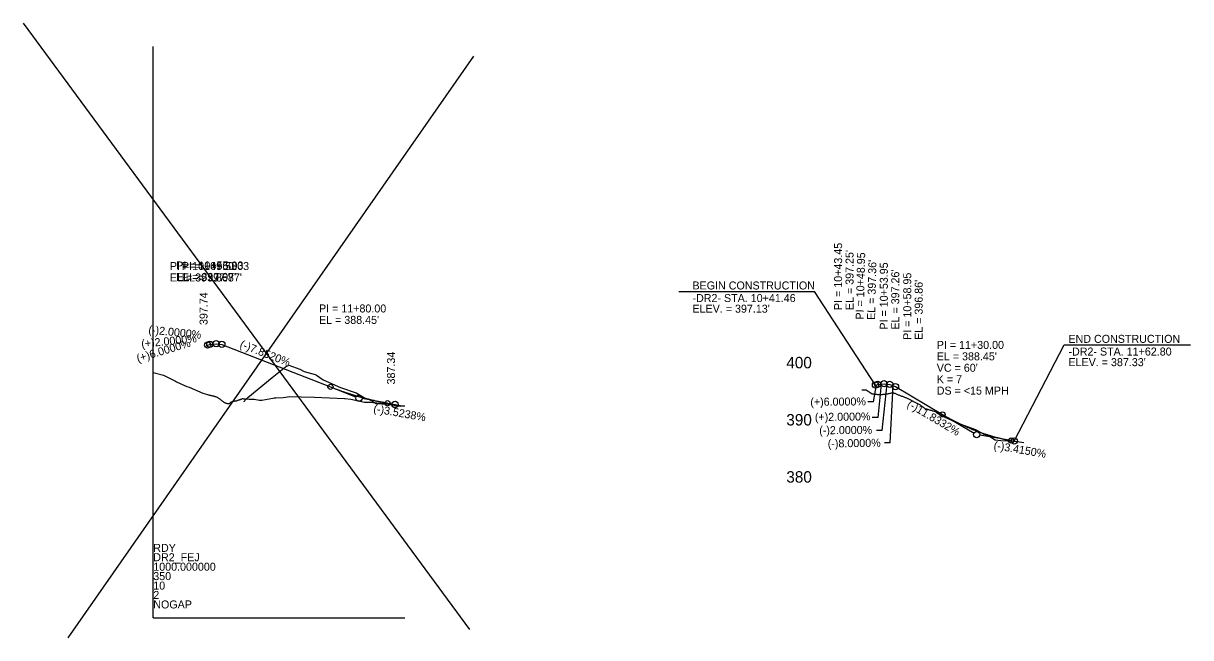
# Model space of a CAD drawing. Extents: x 1625686 to 1640492, y 1161393 to 1175642.
# Drawn here: x 1631857 to 1632878, y 1165908 to 1166445 of the extents above; entities that cross this region are included whole.
import ezdxf

# ---------------------------------------------------------------- set-up
doc = ezdxf.new("R2010")
doc.units = 0
for name, color, linetype in [('Exist Profile Cell', 7, 'Continuous'), ('Exist Vertical Profile Ground Line', 7, 'Continuous'), ('Exist Vertical Profile Vertical Axis Label', 7, 'Continuous'), ('Prop Vertical Profile Curve Label', 7, 'Continuous'), ('Prop Vertical Profile Grade', 7, 'Continuous'), ('Prop Vertical Profile Grade Label', 7, 'Continuous'), ('Prop VPI Label', 7, 'Continuous'), ('Scratch_Level_1', 7, 'Continuous'), ('Scratch_Level_3', 7, 'Continuous')]:
    doc.layers.add(name, color=color, linetype=linetype)

msp = doc.modelspace()

# ---------------------------------------------------------------- linework, layer by layer
at = {"layer": 'Exist Profile Cell'}
for q in [(1631970.3, 1166424.9), (1632190.4, 1165924.9), (1631970.3, 1165924.9)]:
    msp.add_line((1631970.3, 1165924.9), q, dxfattribs=at)
at = {"layer": 'Exist Vertical Profile Ground Line'}
for points in [[(1632049.4, 1166114.3), (1632050, 1166114.6), (1632050.5, 1166115.1), (1632050.9, 1166115.5), (1632052.9, 1166117.6), (1632074.2, 1166135.1), (1632085.9, 1166144.4), (1632088.9, 1166146), (1632098.5, 1166142.6), (1632102.3, 1166140.3), (1632111.8, 1166137.7), (1632113, 1166137.1), (1632119, 1166133.2), (1632134.2, 1166126.5), (1632147.8, 1166121.8), (1632155.1, 1166117.5), (1632160.1, 1166115.7), (1632165.2, 1166112.5), (1632170.3, 1166112), (1632181.8, 1166111.6), (1632188.3, 1166110.5), (1632190.4, 1166110.3)], [(1631970.3, 1166139.6), (1631979.2, 1166137.1), (1631979.7, 1166136.9), (1631983.2, 1166135.2), (1631989.8, 1166131.9), (1631990.5, 1166131.5), (1631999.8, 1166127.3), (1632001.6, 1166126.8), (1632013.6, 1166121.5), (1632017.7, 1166120.3), (1632018.6, 1166120), (1632019, 1166119.9), (1632019.4, 1166119.8), (1632019.9, 1166119.7), (1632020.3, 1166119.6), (1632020.8, 1166119.5), (1632021.5, 1166119.3), (1632022.1, 1166119.2), (1632022.5, 1166119.1), (1632023, 1166119), (1632023.4, 1166118.8), (1632023.9, 1166118.7), (1632024.3, 1166118.6), (1632024.8, 1166118.5), (1632025.2, 1166118.4), (1632025.6, 1166118.2), (1632026.1, 1166118.1), (1632026.5, 1166117.7), (1632027, 1166117.4), (1632027.4, 1166117.1), (1632027.9, 1166116.8), (1632028.3, 1166116.4), (1632028.8, 1166116.1), (1632029.2, 1166115.8), (1632029.6, 1166115.4), (1632030.1, 1166115.1), (1632030.5, 1166114.7), (1632031, 1166114.4), (1632031.4, 1166114.1), (1632031.9, 1166113.7), (1632032.4, 1166113.4), (1632032.7, 1166113.3), (1632033.2, 1166113.1), (1632033.6, 1166113), (1632034.1, 1166112.8), (1632034.5, 1166112.7), (1632035, 1166112.5), (1632035.4, 1166112.5), (1632035.8, 1166112.5), (1632036.3, 1166112.5), (1632036.7, 1166112.5), (1632037.2, 1166112.8), (1632037.6, 1166113.1), (1632038.1, 1166113.5), (1632038.5, 1166113.8), (1632038.9, 1166113.9), (1632039.8, 1166114.2), (1632040.3, 1166114.4), (1632040.7, 1166114.5), (1632041.2, 1166114.6), (1632041.6, 1166114.7), (1632042.1, 1166114.8), (1632042.5, 1166114.8), (1632042.9, 1166114.9), (1632043.4, 1166114.9), (1632043.8, 1166115), (1632044.3, 1166115.2), (1632044.7, 1166115.3), (1632045.2, 1166115.5), (1632045.6, 1166115.6), (1632046, 1166115.8), (1632046.5, 1166115.9), (1632046.9, 1166116.1), (1632047.4, 1166116.3), (1632047.8, 1166116.5), (1632048.3, 1166116.7), (1632048.7, 1166116.7), (1632049.1, 1166116.6), (1632049.6, 1166116.6), (1632050, 1166116.5), (1632050.5, 1166116.5), (1632050.9, 1166116.4), (1632054.3, 1166116.1), (1632058.5, 1166116.2), (1632063.1, 1166115.3), (1632065.3, 1166115.4), (1632071.7, 1166116.4), (1632074.8, 1166117.1), (1632076.2, 1166117.3), (1632077.4, 1166117.4), (1632083.9, 1166117.8), (1632089.7, 1166118.5), (1632099.7, 1166118.4), (1632111.4, 1166117.9), (1632137.5, 1166116.8), (1632138.1, 1166116.7), (1632143.1, 1166116.2), (1632155, 1166113.6), (1632157, 1166113.6), (1632158.6, 1166113.6), (1632160.3, 1166113.7), (1632162.8, 1166113.3), (1632172.2, 1166112.4), (1632173, 1166112.3), (1632178.8, 1166111.3), (1632184.6, 1166110.4), (1632190.4, 1166110.3)]]:
    msp.add_lwpolyline(points, dxfattribs=at)
at = {"layer": 'Prop Vertical Profile Curve Label'}
for centre in [(1632125.3, 1166127), (1632175.3, 1166112.7), (1632660.7, 1166102.9), (1632720.7, 1166080)]:
    msp.add_circle(centre, 2.25, dxfattribs=at)
at = {"layer": 'Prop Vertical Profile Grade'}
for p, q in [((1632017.8, 1166163.6), (1632019.8, 1166164.2)), ((1632019.8, 1166164.2), (1632025.3, 1166164.7)), ((1632025.3, 1166164.7), (1632030.3, 1166164.2)), ((1632030.3, 1166164.2), (1632125.3, 1166127)), ((1632602.1, 1166128.6), (1632604.1, 1166129.2)), ((1632604.1, 1166129.2), (1632609.6, 1166129.7)), ((1632609.6, 1166129.7), (1632614.6, 1166129.2)), ((1632614.6, 1166129.2), (1632619.6, 1166127.2)), ((1632619.6, 1166127.2), (1632660.7, 1166102.9)), ((1632175.3, 1166112.7), (1632181.8, 1166111.6)), ((1632720.7, 1166080), (1632723.5, 1166079.6))]:
    msp.add_line(p, q, dxfattribs=at)
for points in [[(1632125.3, 1166127), (1632126.3, 1166126.6), (1632127.3, 1166126.2), (1632128.3, 1166125.8), (1632129.3, 1166125.4), (1632130.3, 1166125), (1632131.3, 1166124.7), (1632132.3, 1166124.3), (1632133.3, 1166124), (1632134.3, 1166123.6), (1632135.3, 1166123.2), (1632136.3, 1166122.9), (1632137.3, 1166122.6), (1632138.3, 1166122.2), (1632139.3, 1166121.9), (1632140.3, 1166121.6), (1632141.3, 1166121.2), (1632142.3, 1166120.9), (1632143.3, 1166120.6), (1632144.3, 1166120.3), (1632145.3, 1166120), (1632146.3, 1166119.7), (1632147.3, 1166119.4), (1632148.3, 1166119.1), (1632149.3, 1166118.8), (1632150.3, 1166118.5), (1632151.3, 1166118.2), (1632152.3, 1166117.9), (1632153.3, 1166117.7), (1632154.3, 1166117.4), (1632155.3, 1166117.1), (1632156.3, 1166116.9), (1632157.3, 1166116.6), (1632158.3, 1166116.4), (1632159.3, 1166116.1), (1632160.3, 1166115.9), (1632161.3, 1166115.6), (1632162.3, 1166115.4), (1632163.3, 1166115.2), (1632164.3, 1166114.9), (1632165.3, 1166114.7), (1632166.3, 1166114.5), (1632167.3, 1166114.3), (1632168.3, 1166114.1), (1632169.3, 1166113.9), (1632170.3, 1166113.7), (1632171.3, 1166113.5), (1632172.3, 1166113.3), (1632173.3, 1166113.1), (1632174.3, 1166112.9), (1632175.3, 1166112.7)], [(1632660.7, 1166102.9), (1632661.9, 1166102.2), (1632663.1, 1166101.5), (1632664.3, 1166100.8), (1632665.5, 1166100.2), (1632666.7, 1166099.5), (1632667.9, 1166098.8), (1632669.1, 1166098.2), (1632670.3, 1166097.6), (1632671.5, 1166096.9), (1632672.7, 1166096.3), (1632673.9, 1166095.7), (1632675.1, 1166095.1), (1632676.3, 1166094.5), (1632677.5, 1166094), (1632678.7, 1166093.4), (1632679.9, 1166092.9), (1632681.1, 1166092.3), (1632682.3, 1166091.8), (1632683.5, 1166091.3), (1632684.7, 1166090.7), (1632685.9, 1166090.2), (1632687.1, 1166089.7), (1632688.3, 1166089.3), (1632689.5, 1166088.8), (1632690.7, 1166088.3), (1632691.9, 1166087.9), (1632693.1, 1166087.4), (1632694.3, 1166087), (1632695.5, 1166086.6), (1632696.7, 1166086.2), (1632697.9, 1166085.8), (1632699.1, 1166085.4), (1632700.3, 1166085), (1632701.5, 1166084.6), (1632702.7, 1166084.3), (1632703.9, 1166083.9), (1632705.1, 1166083.6), (1632706.3, 1166083.2), (1632707.5, 1166082.9), (1632708.7, 1166082.6), (1632709.9, 1166082.3), (1632711.1, 1166082), (1632712.3, 1166081.7), (1632713.5, 1166081.5), (1632714.7, 1166081.2), (1632715.9, 1166080.9), (1632717.1, 1166080.7), (1632718.3, 1166080.5), (1632719.5, 1166080.3), (1632720.7, 1166080)]]:
    msp.add_spline(points, degree=3, dxfattribs=at)
at = {"layer": 'Prop Vertical Profile Grade Label'}
for p, q in [((1632430.2, 1166210.5), (1632548.8, 1166210.5)), ((1632602.1, 1166128.6), (1632548.8, 1166210.5)), ((1632723.5, 1166079.6), (1632767.1, 1166163.8)), ((1632767.1, 1166163.8), (1632877.8, 1166163.8)), ((1632600.3, 1166113.8), (1632603.1, 1166128.9)), ((1632604.3, 1166100.3), (1632607.4, 1166129.4)), ((1632608, 1166088.8), (1632612.4, 1166129.5)), ((1632615, 1166077.9), (1632617.6, 1166128)), ((1632600.3, 1166113.8), (1632595.3, 1166113.8)), ((1632604.3, 1166100.3), (1632599.3, 1166100.3)), ((1632608, 1166088.8), (1632603, 1166088.8)), ((1632615, 1166077.9), (1632610, 1166077.9))]:
    msp.add_line(p, q, dxfattribs=at)
at = {"layer": 'Prop VPI Label'}
for p, q in [((1632125.3, 1166127), (1632147.8, 1166118.1)), ((1632175.3, 1166112.7), (1632153, 1166116.7)), ((1632660.7, 1166102.9), (1632688.3, 1166086.6)), ((1632720.7, 1166080), (1632693.4, 1166084.7))]:
    msp.add_line(p, q, dxfattribs=at)
for centre in [(1632017.8, 1166163.6), (1632019.8, 1166164.2), (1632025.3, 1166164.7), (1632030.3, 1166164.2), (1632602.1, 1166128.6), (1632604.1, 1166129.2), (1632609.6, 1166129.7), (1632614.6, 1166129.2), (1632619.6, 1166127.2), (1632150.3, 1166117.1), (1632181.8, 1166111.6), (1632690.7, 1166085.2), (1632723.5, 1166079.6)]:
    msp.add_circle(centre, 2.75, dxfattribs=at)
at = {"layer": 'Scratch_Level_1'}
for points in [[(1632590.3, 1166124.4), (1632593.9, 1166124.5), (1632599.2, 1166121), (1632599.8, 1166120.9), (1632600.4, 1166120.8), (1632601, 1166120.7), (1632601.6, 1166120.6), (1632602.2, 1166120.6), (1632602.8, 1166120.5), (1632603.4, 1166120.5), (1632604, 1166120.4), (1632604.6, 1166120.4), (1632605.2, 1166120.4), (1632605.8, 1166120.4), (1632606.4, 1166120.4), (1632607, 1166120.4), (1632607.6, 1166120.4), (1632608.2, 1166120.4), (1632608.8, 1166120.5), (1632609.4, 1166120.5), (1632610, 1166120.6), (1632610.6, 1166120.7), (1632611.2, 1166120.7), (1632611.8, 1166120.8), (1632612.4, 1166120.9), (1632613, 1166121), (1632613.6, 1166121.1), (1632614.2, 1166121.2), (1632614.8, 1166121.4), (1632615.4, 1166121.5), (1632616, 1166121.7), (1632616.7, 1166121.9), (1632617.2, 1166121.8), (1632617.8, 1166121.7), (1632618.5, 1166121.6), (1632619, 1166121.4), (1632619.6, 1166121.1), (1632620.2, 1166120.9), (1632620.8, 1166120.6), (1632621.4, 1166120.4), (1632622, 1166120.1), (1632622.6, 1166119.9), (1632623.2, 1166119.7), (1632623.8, 1166119.4), (1632624.4, 1166119.2), (1632625, 1166118.9), (1632625.6, 1166118.7), (1632626.2, 1166118.5), (1632626.8, 1166118.2), (1632627.4, 1166118), (1632628, 1166117.8), (1632628.6, 1166117.6), (1632629.2, 1166117.3), (1632629.8, 1166117.1), (1632630.4, 1166116.9), (1632631.1, 1166116.6), (1632631.6, 1166116.3), (1632632.2, 1166116), (1632632.8, 1166115.6), (1632633.4, 1166115.2), (1632634, 1166114.8), (1632634.6, 1166114.5), (1632635.2, 1166114.2), (1632635.8, 1166113.9), (1632636.4, 1166113.6), (1632637, 1166113.3), (1632637.6, 1166113), (1632638.2, 1166112.7), (1632638.8, 1166112.4), (1632639.4, 1166112.1), (1632640, 1166111.8), (1632640.6, 1166111.5), (1632641.2, 1166111.2), (1632641.8, 1166110.7), (1632642.4, 1166110.3), (1632643, 1166109.8), (1632643.6, 1166109.4), (1632644.2, 1166108.9), (1632644.8, 1166108.5), (1632645.4, 1166108.1), (1632646, 1166107.9), (1632646.6, 1166107.7), (1632647.2, 1166107.5), (1632647.8, 1166107.4), (1632648.4, 1166107.2), (1632649, 1166107), (1632649.6, 1166106.8), (1632650.2, 1166106.7), (1632650.8, 1166106.5), (1632651.4, 1166106.3), (1632652, 1166106.1), (1632652.5, 1166106), (1632653.4, 1166105.7), (1632653.7, 1166105.6), (1632654.3, 1166105.3), (1632654.9, 1166105), (1632655.5, 1166104.6), (1632660.6, 1166101.3), (1632675.8, 1166094.5), (1632689.5, 1166089.8), (1632696.8, 1166085.5)], [(1632696.8, 1166085.5), (1632701.8, 1166083.7), (1632706.9, 1166080.5), (1632711.9, 1166080), (1632723.5, 1166079.6), (1632730, 1166078.5), (1632732, 1166078.3)]]:
    msp.add_lwpolyline(points, dxfattribs=at)
at = {"layer": 'Scratch_Level_3'}
for p, q in [((1631856.6, 1166445.1), (1632247, 1165914.7)), ((1631896, 1165907.5), (1632250.6, 1166416.4))]:
    msp.add_line(p, q, dxfattribs=at)

# ---------------------------------------------------------------- texts
at = {"layer": 'Exist Profile Cell'}
for s, p in [('RDY', (1631970.3, 1165982.6)), ('DR2_FEJ', (1631970.3, 1165974.4)), ('1000.000000', (1631970.3, 1165966.1)), ('350', (1631970.3, 1165957.9)), ('10', (1631970.3, 1165949.6)), ('2', (1631970.3, 1165941.4)), ('NOGAP', (1631970.3, 1165933.1))]:
    msp.add_text(s, height=7, dxfattribs=at).set_placement(p)
at = {"layer": 'Exist Vertical Profile Vertical Axis Label'}
for s, p in [('400', (1632524.1, 1166143.2)), ('390', (1632524.1, 1166093.2)), ('380', (1632524.1, 1166043.2))]:
    msp.add_text(s, height=10, dxfattribs=at).set_placement(p)
at = {"layer": 'Prop Vertical Profile Curve Label'}
for s, p in [("VC = 60'", (1632655.7, 1166140.2)), ('K = 7', (1632655.7, 1166130.2)), ('DS = <15 MPH', (1632655.7, 1166120.2))]:
    msp.add_text(s, height=7, dxfattribs=at).set_placement(p)
at = {"layer": 'Prop Vertical Profile Grade Label'}
for s, rotation, p in [('(+)2.0000%', 5.7106, (1631960.2, 1166161.2)), ('(-)2.0000%', 354.2894, (1631965.8, 1166173.7)), ('(+)6.0000%', 16.6992, (1631956.9, 1166148.4)), ('(-)7.8520%', 338.5651, (1632045.4, 1166161.6)), ('(-)3.5238%', 350.0076, (1632162.5, 1166104.8)), ('(+)6.0000%', 0.4229, (1632545.1, 1166110.4)), ('(-)11.8332%', 329.3889, (1632629.1, 1166110)), ('(+)2.0000%', 0.6388, (1632549.1, 1166097.1)), ('(-)2.0000%', 0.4207, (1632552.9, 1166085.5)), ('(-)8.0000%', 0.9396, (1632560.4, 1166073.9)), ('(-)3.4150%', 350.3102, (1632705.1, 1166072.6))]:
    msp.add_text(s, height=7, rotation=rotation, dxfattribs=at).set_placement(p)
at = {"layer": 'Prop VPI Label'}
for s, rotation, p in [('PI = 10+43.45', 90, (1632572.9, 1166194.2)), ("EL = 397.25'", 90, (1632582.9, 1166194.2)), ('PI = 10+48.95', 88.5892, (1632591.7, 1166185.8)), ("EL = 397.36'", 88.5892, (1632601.7, 1166185.5)), ('PI = 10+53.95', 90, (1632612.9, 1166177.1)), ("EL = 397.26'", 90, (1632622.9, 1166177.1)), ('PI = 10+58.95', 90, (1632633.4, 1166168.1)), ("EL = 396.86'", 90, (1632643.4, 1166168.1)), ('397.74', 90, (1632017.8, 1166181.1)), ('387.34', 90, (1632181.8, 1166129.1))]:
    msp.add_text(s, height=7, rotation=rotation, dxfattribs=at).set_placement(p)
for s, p in [('PI = 10+49.53', (1631984.8, 1166229.2)), ('PI = 10+55.03', (1631990.3, 1166229.7)), ('PI = 10+60.03', (1631995.3, 1166229.2)), ("EL = 397.86'", (1631984.8, 1166219.2)), ("EL = 397.97'", (1631990.3, 1166219.7)), ("EL = 397.87'", (1631995.3, 1166219.2)), ('BEGIN CONSTRUCTION', (1632442, 1166212.2)), ('-DR2- STA. 10+41.46', (1632442, 1166201.2)), ('PI = 11+80.00', (1632115.3, 1166192.1)), ("ELEV. = 397.13'", (1632442, 1166191.9)), ("EL = 388.45'", (1632115.3, 1166182.1)), ('END CONSTRUCTION', (1632770.9, 1166165.5)), ('PI = 11+30.00', (1632655.7, 1166160.2)), ('-DR2- STA. 11+62.80', (1632770.9, 1166154.4)), ("EL = 388.45'", (1632655.7, 1166150.2)), ("ELEV. = 387.33'", (1632770.9, 1166145.1))]:
    msp.add_text(s, height=7, dxfattribs=at).set_placement(p)

doc.saveas('drawing.dxf')
